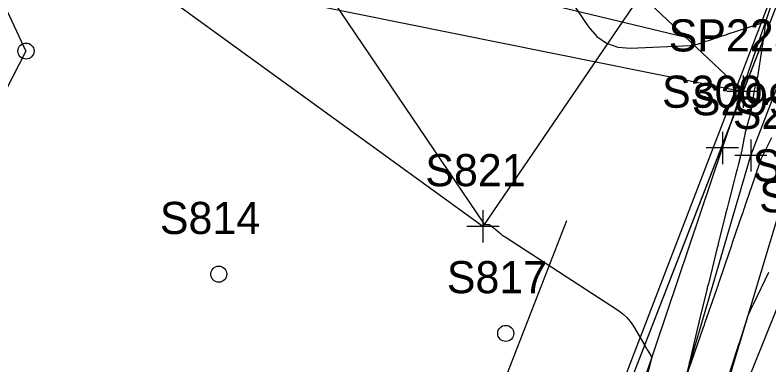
# Model space of a CAD drawing. Extents: x 816928 to 825690, y 436959 to 448212.
# Drawn here: x 818704.4 to 818798.2, y 444837.4 to 444881 of the extents above; entities that cross this region are included whole.
import ezdxf

# ---------------------------------------------------------------- set-up
doc = ezdxf.new("R2010")
doc.units = 0
for name, color, linetype in [('DESIGN - SCRATCH - User 1', 7, 'Continuous'), ('SURVEY - CENTERLINE - Preliminary Text', 7, 'Continuous'), ('SURVEY - CONTOURS - Intermediate with optional Text', 7, 'Continuous'), ('SURVEY - DTM - Breaklines', 7, 'Continuous'), ('SURVEY - DTM - Breaklines - Points - Locators', 7, 'Continuous'), ('SURVEY - DTM - Breaklines - Points - Numbers', 7, 'Continuous'), ('SURVEY - DTM - Spot Points - Locators', 7, 'Continuous'), ('SURVEY - DTM - Spot Points - Point Numbers', 7, 'Continuous'), ('SURVEY - NON-TRANSPORTATION - Features', 7, 'Continuous'), ('SURVEY - PROPERTY - Parcels', 7, 'Continuous'), ('SURVEY - PROPERTY - Property Lines', 7, 'Continuous'), ('SURVEY - PROPERTY - Property Lines - Points - Locators', 7, 'Continuous'), ('SURVEY - PROPERTY - Property Lines - Points - Numbers', 7, 'Continuous'), ('SURVEY - PROPERTY - Property Lines Text', 7, 'Continuous'), ('SURVEY - PROPERTY - ROW Lines', 7, 'Continuous'), ('SURVEY - PROPERTY - ROW Lines Text', 7, 'Continuous'), ('SURVEY - PROPERTY - Station and Offset Flags', 7, 'Continuous'), ('SURVEY - TRANSPORTATION - Roads - Points - Numbers', 7, 'Continuous'), ('SURVEY - UTILITIES - Gas - Points - Numbers', 7, 'Continuous'), ('SURVEY - UTILITIES - Gas with Text', 7, 'Continuous'), ('SURVEY - VEGETATION - Features - Points - Locators', 7, 'Continuous'), ('SURVEY - VEGETATION - Features - Points - Numbers', 7, 'Continuous'), ('SURVEY - VEGETATION - Features with Text', 7, 'Continuous')]:
    doc.layers.add(name, color=color, linetype=linetype)

msp = doc.modelspace()

# ---------------------------------------------------------------- linework, layer by layer
at = {"layer": 'DESIGN - SCRATCH - User 1'}
msp.add_lwpolyline([(818715.142, 445099.822), (818745.74, 445051.115), (818754.139, 445016.546), (818742.604, 444943.58), (818728.388, 444935.98), (818679.21, 444933.136), (818705.722, 444876.505), (818677.894, 444822.371)], dxfattribs=at)
at = {"layer": 'SURVEY - CONTOURS - Intermediate with optional Text'}
for points in [[(818739.636, 444889.182), (818762.686, 444855.066), (818762.743, 444854.999), (818762.811, 444854.952), (818762.889, 444854.926), (818762.977, 444854.92), (818763.401, 444854.939), (818763.407, 444854.938), (818763.412, 444854.937), (818763.417, 444854.935), (818763.422, 444854.932), (818763.436, 444854.92), (818763.439, 444854.918), (818763.442, 444854.915), (818763.445, 444854.913), (818763.448, 444854.91), (818763.535, 444854.839), (818763.554, 444854.823), (818763.573, 444854.808), (818763.592, 444854.793), (818763.61, 444854.777), (818763.73, 444854.679), (818763.756, 444854.658), (818763.781, 444854.637), (818763.807, 444854.616), (818763.833, 444854.595), (818764.066, 444854.404), (818764.116, 444854.363), (818764.166, 444854.322), (818764.216, 444854.281), (818764.266, 444854.24), (818764.86, 444853.754), (818764.989, 444853.652), (818765.12, 444853.553), (818765.254, 444853.458), (818765.391, 444853.367), (818779.513, 444844.201), (818780.062, 444843.799), (818780.553, 444843.343), (818780.988, 444842.832), (818781.366, 444842.267), (818782.795, 444839.846), (818782.897, 444839.674), (818782.998, 444839.502), (818783.1, 444839.33), (818783.201, 444839.158), (818783.532, 444838.597), (818783.59, 444838.475), (818783.621, 444838.349), (818783.625, 444838.22), (818783.603, 444838.086), (818782.756, 444834.887)], [(818771.299, 444886.139), (818775.766, 444879.527), (818776.803, 444878.313), (818778.026, 444877.467), (818779.435, 444876.989), (818781.028, 444876.879), (818788.424, 444877.206), (818788.659, 444877.225), (818788.892, 444877.259), (818789.121, 444877.309), (818789.348, 444877.375), (818790.084, 444877.616), (818790.241, 444877.668), (818790.399, 444877.72), (818790.556, 444877.772), (818790.714, 444877.823), (818792.034, 444878.256), (818792.317, 444878.349), (818792.6, 444878.442), (818792.883, 444878.535), (818793.166, 444878.627), (818795.63, 444879.436), (818795.884, 444879.519), (818796.138, 444879.602), (818796.392, 444879.686), (818796.646, 444879.769), (818797.475, 444880.041), (818797.628, 444880.069), (818797.731, 444880.036), (818797.785, 444879.941), (818797.788, 444879.786), (818797.657, 444878.655), (818797.648, 444878.581), (818797.636, 444878.507), (818797.622, 444878.434), (818797.606, 444878.362), (818797.551, 444878.125), (818797.539, 444878.074), (818797.529, 444878.023), (818797.52, 444877.972), (818797.512, 444877.92), (818796.967, 444874.092), (818796.925, 444873.825), (818796.877, 444873.559), (818796.821, 444873.295), (818796.758, 444873.032), (818796.542, 444872.176), (818796.497, 444871.992), (818796.457, 444871.807), (818796.42, 444871.622), (818796.387, 444871.436), (818796.067, 444869.498), (818795.993, 444869.083), (818795.909, 444868.671), (818795.815, 444868.262), (818795.711, 444867.854), (818795.342, 444866.481), (818795.266, 444866.186), (818795.196, 444865.889), (818795.132, 444865.592), (818795.073, 444865.293), (818794.827, 444863.966), (818794.813, 444863.896), (818794.798, 444863.826), (818794.781, 444863.757), (818794.763, 444863.688), (818794.701, 444863.463), (818794.688, 444863.415), (818794.675, 444863.366), (818794.663, 444863.318), (818794.651, 444863.269), (818794.456, 444862.482), (818794.414, 444862.314), (818794.371, 444862.145), (818794.326, 444861.977), (818794.281, 444861.809), (818794.073, 444861.05), (818794.029, 444860.887), (818793.986, 444860.724), (818793.944, 444860.56), (818793.903, 444860.396), (818793.222, 444857.622), (818793.179, 444857.45), (818793.135, 444857.278), (818793.09, 444857.106), (818793.044, 444856.935), (818792.892, 444856.375), (818792.86, 444856.255), (818792.828, 444856.135), (818792.798, 444856.015), (818792.768, 444855.894), (818791.98, 444852.669), (818791.948, 444852.538), (818791.914, 444852.406), (818791.88, 444852.275), (818791.845, 444852.144), (818791.73, 444851.717), (818791.706, 444851.626), (818791.682, 444851.534), (818791.658, 444851.442), (818791.636, 444851.35), (818790.754, 444847.715), (818790.731, 444847.623), (818790.708, 444847.531), (818790.684, 444847.439), (818790.66, 444847.347), (818790.579, 444847.048), (818790.562, 444846.984), (818790.546, 444846.92), (818790.53, 444846.855), (818790.514, 444846.791), (818789.541, 444842.76), (818789.528, 444842.706), (818789.514, 444842.652), (818789.5, 444842.598), (818789.486, 444842.544), (818789.439, 444842.369), (818789.43, 444842.331), (818789.42, 444842.294), (818789.411, 444842.256), (818789.401, 444842.218), (818788.341, 444837.803), (818788.337, 444837.786), (818788.333, 444837.769), (818788.329, 444837.752), (818788.324, 444837.735), (818788.31, 444837.68), (818788.307, 444837.668), (818788.304, 444837.656), (818788.301, 444837.644), (818788.298, 444837.633), (818787.936, 444836.116)], [(818788.002, 444836.097), (818788.544, 444837.638), (818788.55, 444837.655), (818788.556, 444837.672), (818788.562, 444837.689), (818788.567, 444837.707), (818788.585, 444837.763), (818788.589, 444837.775), (818788.593, 444837.787), (818788.597, 444837.799), (818788.601, 444837.811), (818790.157, 444842.253), (818790.175, 444842.304), (818790.192, 444842.356), (818790.209, 444842.408), (818790.226, 444842.46), (818790.28, 444842.63), (818790.291, 444842.667), (818790.303, 444842.703), (818790.316, 444842.739), (818790.328, 444842.775), (818791.759, 444846.879), (818791.788, 444846.963), (818791.816, 444847.047), (818791.843, 444847.131), (818791.871, 444847.215), (818791.958, 444847.491), (818791.977, 444847.55), (818791.996, 444847.609), (818792.016, 444847.668), (818792.036, 444847.727), (818793.351, 444851.516), (818793.39, 444851.63), (818793.429, 444851.744), (818793.466, 444851.858), (818793.503, 444851.973), (818793.621, 444852.347), (818793.647, 444852.428), (818793.673, 444852.508), (818793.7, 444852.588), (818793.727, 444852.667), (818794.936, 444856.162), (818794.984, 444856.304), (818795.032, 444856.446), (818795.078, 444856.589), (818795.124, 444856.732), (818795.272, 444857.199), (818795.304, 444857.299), (818795.336, 444857.399), (818795.37, 444857.498), (818795.403, 444857.598), (818796.568, 444860.979), (818796.598, 444861.066), (818796.627, 444861.153), (818796.655, 444861.24), (818796.683, 444861.328), (818796.774, 444861.614), (818796.793, 444861.675), (818796.813, 444861.736), (818796.833, 444861.797), (818796.854, 444861.858), (818797.15, 444862.718), (818797.216, 444862.901), (818797.289, 444863.081), (818797.368, 444863.259), (818797.453, 444863.434), (818798.631, 444865.76)], [(818793.069, 444835.473), (818794.551, 444840.137), (818794.553, 444840.144), (818794.555, 444840.151), (818794.558, 444840.159), (818794.56, 444840.166), (818794.569, 444840.19), (818794.571, 444840.195), (818794.572, 444840.2), (818794.574, 444840.206), (818794.576, 444840.211), (818795.529, 444843.215), (818795.595, 444843.411), (818795.667, 444843.604), (818795.745, 444843.795), (818795.83, 444843.984), (818796.212, 444844.798), (818796.227, 444844.827), (818796.242, 444844.856), (818796.257, 444844.885), (818796.274, 444844.913), (818796.328, 444845.006), (818796.339, 444845.026), (818796.35, 444845.046), (818796.361, 444845.066), (818796.371, 444845.086), (818798.255, 444848.967)]]:
    msp.add_lwpolyline(points, dxfattribs=at)
at = {"layer": 'SURVEY - DTM - Breaklines'}
for points in [[(818668.595, 444528.248), (818685.72, 444574.968), (818701.794, 444621.45), (818719.062, 444668.194), (818736.238, 444715.249), (818753.948, 444762.85), (818774.464, 444810.969), (818792.449, 444864.448), (818805.628, 444902.916), (818824.667, 444952.978), (818842.703, 444999.992), (818860.037, 445043.657), (818874.783, 445092.697), (818880.828, 445100.462), (818882.708, 445127.319), (818888.697, 445139.719), (818911.769, 445177.181)], [(818674.595, 444526.594), (818691.482, 444572.447), (818707.878, 444620.16), (818723.912, 444667.229), (818740.639, 444713.784), (818759.184, 444760.748), (818780.007, 444808.946), (818796, 444863.508), (818810.795, 444901.838), (818829.914, 444950.597), (818849.199, 444995.994), (818867.147, 445042.084), (818885.66, 445087.698), (818887.911, 445097.82), (818891.186, 445123.694), (818896.177, 445136.062), (818917.377, 445175.791)], [(818676.308, 444526.27), (818695.981, 444570.723), (818712.39, 444618.98), (818728.83, 444665.288), (818745.895, 444712.28), (818764.807, 444759.048), (818784.52, 444806.667), (818801.14, 444861.811), (818818.983, 444900.087), (818838.243, 444946.217), (818855.869, 444992.165), (818873.704, 445038.582), (818892.288, 445085.577), (818894.59, 445096.559), (818896.482, 445123.312), (818901.189, 445133.745), (818919.534, 445174.233), (818947.165, 445168.058)]]:
    msp.add_lwpolyline(points, dxfattribs=at)
at = {"layer": 'SURVEY - DTM - Breaklines - Points - Locators'}
for p, q in [((818792.449, 444866.448), (818792.449, 444862.448)), ((818796, 444865.508), (818796, 444861.508)), ((818794.449, 444864.448), (818790.449, 444864.448)), ((818798, 444863.508), (818794, 444863.508))]:
    msp.add_line(p, q, dxfattribs=at)
at = {"layer": 'SURVEY - DTM - Spot Points - Locators'}
for centre in [(818705.722, 444876.505), (818729.732, 444848.734), (818765.47, 444841.367)]:
    msp.add_circle(centre, 1, dxfattribs=at)
at = {"layer": 'SURVEY - NON-TRANSPORTATION - Features'}
msp.add_lwpolyline([(818640.147, 444520.892), (818666.049, 444525.128), (818695.511, 444604.302), (818745.612, 444742.32), (818768.232, 444804.488), (818806.137, 444902.965), (818848.514, 445015.373), (818878.723, 445102.028)], dxfattribs=at)
at = {"layer": 'SURVEY - PROPERTY - Parcels'}
for p, q in [((818795.05, 444871.453), (818850.081, 445012.805)), ((818780.722, 444885.014), (818795.05, 444871.453)), ((818795.05, 444871.453), (818780.722, 444885.014)), ((818717.176, 444671.423), (818795.05, 444871.453))]:
    msp.add_line(p, q, dxfattribs=at)
at = {"layer": 'SURVEY - PROPERTY - Property Lines'}
msp.add_line((818780.722, 444885.014), (818795.05, 444871.453), dxfattribs=at)
at = {"layer": 'SURVEY - PROPERTY - Property Lines - Points - Locators'}
for p, q in [((818795.05, 444873.453), (818795.05, 444869.453)), ((818797.05, 444871.453), (818793.05, 444871.453))]:
    msp.add_line(p, q, dxfattribs=at)
at = {"layer": 'SURVEY - PROPERTY - Property Lines Text'}
msp.add_lwpolyline([(818754.742, 444886.223), (818787.886, 444878.233)], dxfattribs=at)
at = {"layer": 'SURVEY - PROPERTY - ROW Lines'}
msp.add_line((818717.176, 444671.423), (818850.081, 445012.805), dxfattribs=at)
at = {"layer": 'SURVEY - PROPERTY - ROW Lines Text'}
msp.add_line((818773.046, 444855.387), (818746.732, 444787.798), dxfattribs=at)
at = {"layer": 'SURVEY - PROPERTY - Station and Offset Flags'}
msp.add_lwpolyline([(818734.835, 444883.636), (818795.05, 444871.453)], dxfattribs=at)
at = {"layer": 'SURVEY - UTILITIES - Gas with Text'}
msp.add_lwpolyline([(818677.986, 444524.549), (818704.191, 444595.26), (818728.998, 444664.068), (818764.629, 444758.415), (818803.581, 444855.269), (818837.396, 444944.843), (818872.359, 445029.489), (818905.906, 445097.999), (818946.069, 445164.692)], dxfattribs=at)
at = {"layer": 'SURVEY - VEGETATION - Features - Points - Locators'}
for p, q in [((818762.636, 444856.685), (818762.636, 444852.685)), ((818764.636, 444854.685), (818760.636, 444854.685))]:
    msp.add_line(p, q, dxfattribs=at)
at = {"layer": 'SURVEY - VEGETATION - Features with Text'}
msp.add_lwpolyline([(818754.139, 445016.546), (818775.014, 444950.045), (818785.739, 444888.594), (818762.636, 444854.685), (818713.118, 444890.56), (818679.21, 444933.136)], dxfattribs=at)

# ---------------------------------------------------------------- texts
at = {"layer": 'SURVEY - CENTERLINE - Preliminary Text'}
msp.add_text('N 21%%d 16\' 18" E', height=6, rotation=68.72845, dxfattribs=at).set_placement((818794.749, 444805.662))
at = {"layer": 'SURVEY - DTM - Breaklines - Points - Numbers'}
for s, p in [('S300', (818784.94, 444869.448)), ('S299', (818788.648, 444868.508)), ('S298', (818793.757, 444866.811))]:
    msp.add_text(s, height=4, dxfattribs=at).set_placement(p)
at = {"layer": 'SURVEY - DTM - Spot Points - Point Numbers'}
for s, p in [('S814', (818722.396, 444853.734)), ('S817', (818758.134, 444846.367))]:
    msp.add_text(s, height=4, dxfattribs=at).set_placement(p)
at = {"layer": 'SURVEY - PROPERTY - Property Lines - Points - Numbers'}
msp.add_text('SP225', height=4, dxfattribs=at).set_placement((818785.763, 444876.453))
at = {"layer": 'SURVEY - TRANSPORTATION - Roads - Points - Numbers'}
msp.add_text('S168', height=4, dxfattribs=at).set_placement((818797.034, 444856.441))
at = {"layer": 'SURVEY - UTILITIES - Gas - Points - Numbers'}
msp.add_text('S769', height=4, dxfattribs=at).set_placement((818796.23, 444860.269))
at = {"layer": 'SURVEY - VEGETATION - Features - Points - Numbers'}
msp.add_text('S821', height=4, dxfattribs=at).set_placement((818755.457, 444859.685))

doc.saveas('drawing.dxf')
